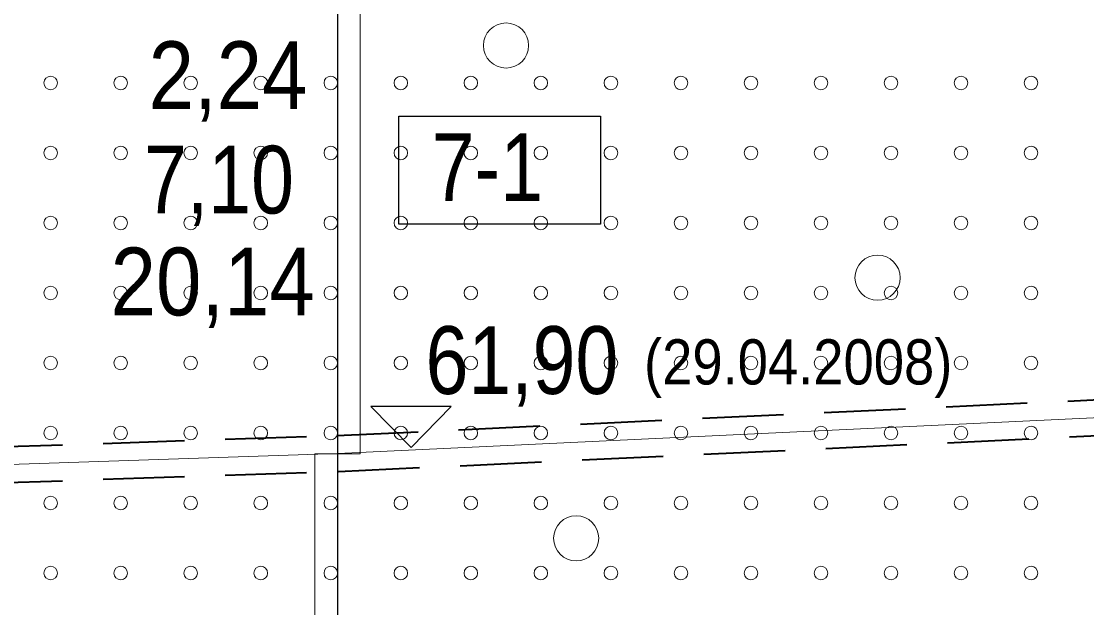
# Model space of a CAD drawing. Extents: x 640121 to 640955, y 6441885 to 6442246.
# Drawn here: x 640771.79 to 640818.96, y 6442124.85 to 6442150.81 of the extents above; entities that cross this region are included whole.
import ezdxf
from ezdxf.enums import TextEntityAlignment as Align

# ---------------------------------------------------------------- set-up
doc = ezdxf.new("R2010")
doc.units = 0
doc.header["$LTSCALE"] = 1.2
doc.linetypes.add('MEDIUM_DASHED', pattern=[4.5, 3, -1.5])
for name, color, linetype, lineweight in [('32', 7, 'Continuous', 13), ('33', 7, 'Continuous', 13), ('34', 7, 'Continuous', 25), ('35', 7, 'Continuous', 35), ('43', 7, 'Continuous', 13), ('47', 7, 'Continuous', 13)]:
    doc.layers.add(name, color=color, linetype=linetype, lineweight=lineweight)

msp = doc.modelspace()

# ---------------------------------------------------------------- linework, layer by layer
at = {"layer": '32', "lineweight": 25}
msp.add_line((640785.79, 6442156.66), (640785.79, 6442096.66), dxfattribs=at)
at = {"layer": '33'}
for points in [[(640786.79, 6442131.66), (640786.79, 6442151.66), (640786.21, 6442151.66), (640785.79, 6442151.66), (640785.79, 6442131.66)], [(640784.79, 6442131.66), (640784.79, 6442102.66), (640785.79, 6442102.66), (640785.79, 6442131.66)]]:
    msp.add_lwpolyline(points, close=True, dxfattribs=at)
at = {"layer": '33', "lineweight": 25}
msp.add_lwpolyline([(640788.5, 6442146.61), (640797.43, 6442146.61), (640797.43, 6442141.83), (640788.5, 6442141.83)], close=True, dxfattribs=at)
at = {"layer": '34', "lineweight": 13}
msp.add_lwpolyline([(640635.03, 6442126.63), (640785.8, 6442131.67), (640874.6, 6442135.86), (640933.07, 6442137.4)], dxfattribs=at)
at = {"layer": '34'}
msp.add_lwpolyline([(640787.26, 6442133.75), (640789.05, 6442131.94), (640790.83, 6442133.75)], close=True, dxfattribs=at)
at = {"layer": '35', "linetype": 'MEDIUM_DASHED'}
for points in [[(640651.29, 6442127.97), (640785.76, 6442132.47), (640872.99, 6442136.59)], [(640651.29, 6442126.37), (640785.83, 6442130.88), (640872.99, 6442134.99)]]:
    msp.add_lwpolyline(points, dxfattribs=at)
at = {"layer": '43'}
for centre in [(640773.094, 6442148.081), (640776.194, 6442148.081), (640779.294, 6442148.081), (640782.394, 6442148.081), (640785.494, 6442148.081), (640788.594, 6442148.081), (640791.694, 6442148.081), (640794.794, 6442148.081), (640797.894, 6442148.081), (640800.994, 6442148.081), (640804.094, 6442148.081), (640807.194, 6442148.081), (640810.294, 6442148.081), (640813.394, 6442148.081), (640816.494, 6442148.081), (640773.094, 6442144.981), (640776.194, 6442144.981), (640779.294, 6442144.981), (640782.394, 6442144.981), (640785.494, 6442144.981), (640788.594, 6442144.981), (640791.694, 6442144.981), (640794.794, 6442144.981), (640797.894, 6442144.981), (640800.994, 6442144.981), (640804.094, 6442144.981), (640807.194, 6442144.981), (640810.294, 6442144.981), (640813.394, 6442144.981), (640816.494, 6442144.981), (640773.094, 6442141.881), (640776.194, 6442141.881), (640779.294, 6442141.881), (640782.394, 6442141.881), (640785.494, 6442141.881), (640788.594, 6442141.881), (640791.694, 6442141.881), (640794.794, 6442141.881), (640797.894, 6442141.881), (640800.994, 6442141.881), (640804.094, 6442141.881), (640807.194, 6442141.881), (640810.294, 6442141.881), (640813.394, 6442141.881), (640816.494, 6442141.881), (640773.094, 6442138.781), (640776.194, 6442138.781), (640779.294, 6442138.781), (640782.394, 6442138.781), (640785.494, 6442138.781), (640788.594, 6442138.781), (640791.694, 6442138.781), (640794.794, 6442138.781), (640797.894, 6442138.781), (640800.994, 6442138.781), (640804.094, 6442138.781), (640807.194, 6442138.781), (640810.294, 6442138.781), (640813.394, 6442138.781), (640816.494, 6442138.781), (640773.094, 6442135.681), (640776.194, 6442135.681), (640779.294, 6442135.681), (640782.394, 6442135.681), (640785.494, 6442135.681), (640788.594, 6442135.681), (640791.694, 6442135.681), (640794.794, 6442135.681), (640797.894, 6442135.681), (640800.994, 6442135.681), (640804.094, 6442135.681), (640807.194, 6442135.681), (640810.294, 6442135.681), (640813.394, 6442135.681), (640816.494, 6442135.681), (640773.094, 6442132.581), (640776.194, 6442132.581), (640779.294, 6442132.581), (640782.394, 6442132.581), (640785.494, 6442132.581), (640788.594, 6442132.581), (640791.694, 6442132.581), (640794.794, 6442132.581), (640797.894, 6442132.581), (640800.994, 6442132.581), (640804.094, 6442132.581), (640807.194, 6442132.581), (640810.294, 6442132.581), (640813.394, 6442132.581), (640816.494, 6442132.581), (640773.094, 6442129.481), (640776.194, 6442129.481), (640779.294, 6442129.481), (640782.394, 6442129.481), (640785.494, 6442129.481), (640788.594, 6442129.481), (640791.694, 6442129.481), (640794.794, 6442129.481), (640797.894, 6442129.481), (640800.994, 6442129.481), (640804.094, 6442129.481), (640807.194, 6442129.481), (640810.294, 6442129.481), (640813.394, 6442129.481), (640816.494, 6442129.481), (640773.094, 6442126.381), (640776.194, 6442126.381), (640779.294, 6442126.381), (640782.394, 6442126.381), (640785.494, 6442126.381), (640788.594, 6442126.381), (640791.694, 6442126.381), (640794.794, 6442126.381), (640797.894, 6442126.381), (640800.994, 6442126.381), (640804.094, 6442126.381), (640807.194, 6442126.381), (640810.294, 6442126.381), (640813.394, 6442126.381), (640816.494, 6442126.381)]:
    msp.add_circle(centre, 0.3, dxfattribs=at)
at = {"layer": '47'}
for centre in [(640793.252, 6442149.737), (640809.699, 6442139.458), (640796.356, 6442127.919)]:
    msp.add_circle(centre, 1, dxfattribs=at)

# ---------------------------------------------------------------- texts
at = {"layer": '32', "width": 0.9}
for s, p in [('2,24', (640780.945, 6442146.92)), ('20,14', (640780.265, 6442137.79))]:
    msp.add_text(s, height=3, dxfattribs=at).set_placement(p, align=Align.CENTER)
at = {"layer": '33', "width": 0.85}
for s, p in [('7-1', (640792.425, 6442142.85)), ('7,10', (640780.545, 6442142.3))]:
    msp.add_text(s, height=3, dxfattribs=at).set_placement(p, align=Align.CENTER)
at = {"layer": '34'}
for s, height, width, p in [('61,90', 3, 0.85, (640793.955, 6442134.31)), ('(29.04.2008)', 2, 0.9, (640806.185, 6442134.73))]:
    msp.add_text(s, height=height, dxfattribs=dict(at, width=width)).set_placement(p, align=Align.CENTER)

doc.saveas('drawing.dxf')
